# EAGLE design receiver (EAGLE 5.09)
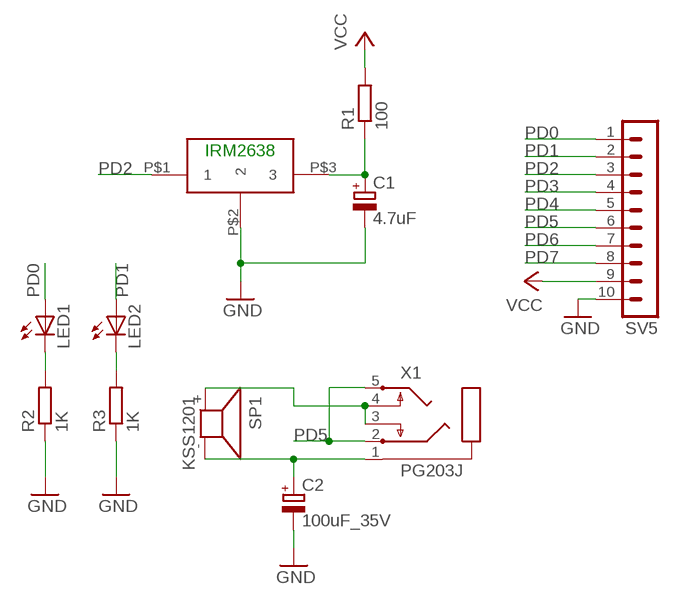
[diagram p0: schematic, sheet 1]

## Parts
C1  4.7uF  CPOL-EUE2.5-5  [E2,5-5]
C2  100uF_35V  CPOL-EUE1.8-4  [E1,8-4]
IRM2638  2638  [IRM2638]
LED1  LED5MM  [LED5MM]
LED2  LED5MM  [LED5MM]
R1  100  R-EU_0204/7  [0204/7]
R2  1K  R-EU_0204/7  [0204/7]
R3  1K  R-EU_0204/7  [0204/7]
SP1  KSS1201  [KSS1201]
SV5  MA10-1  [MA10-1]
X1  PG203J  [PG203J]

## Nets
GND: C1.- C2.- IRM2638.P$2 R2.1 R3.1 SV5.10
N$1: C2.+ SP1.- X1.1
N$2: C1.+ IRM2638.P$3 R1.1
N$3: SP1.+ X1.3 X1.4
N$4: LED1.K(C) R2.2
N$5: LED2.K(C) R3.2
PD0: LED1.A SV5.1
PD1: LED2.A SV5.2
PD2: IRM2638.P$1 SV5.3
PD3: SV5.4
PD4: SV5.5
PD5: SV5.6 X1.2 X1.5
PD6: SV5.7
PD7: SV5.8
VCC: R1.2 SV5.9

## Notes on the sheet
- IRM2638

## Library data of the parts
C1 = resistor:CPOL-EU: POLARIZED CAPACITOR, European symbol
C2 = rcl:CPOL-EU: POLARIZED CAPACITOR, European symbol
IRM2638 = 2638:2638
LED1 LED2 = led:LED: LED
R1-R3 = resistor:R-EU_: RESISTOR, European symbol
SP1 = buzzer:KSS1201: SPEAKER
SV5 = con-lstb:MA10-1: PIN HEADER
X1 = con-hirschmann:PG203J: MIC/HEADPHONE JACK KS-S stereo microphone/headphone jack PG203JN (Schukat)

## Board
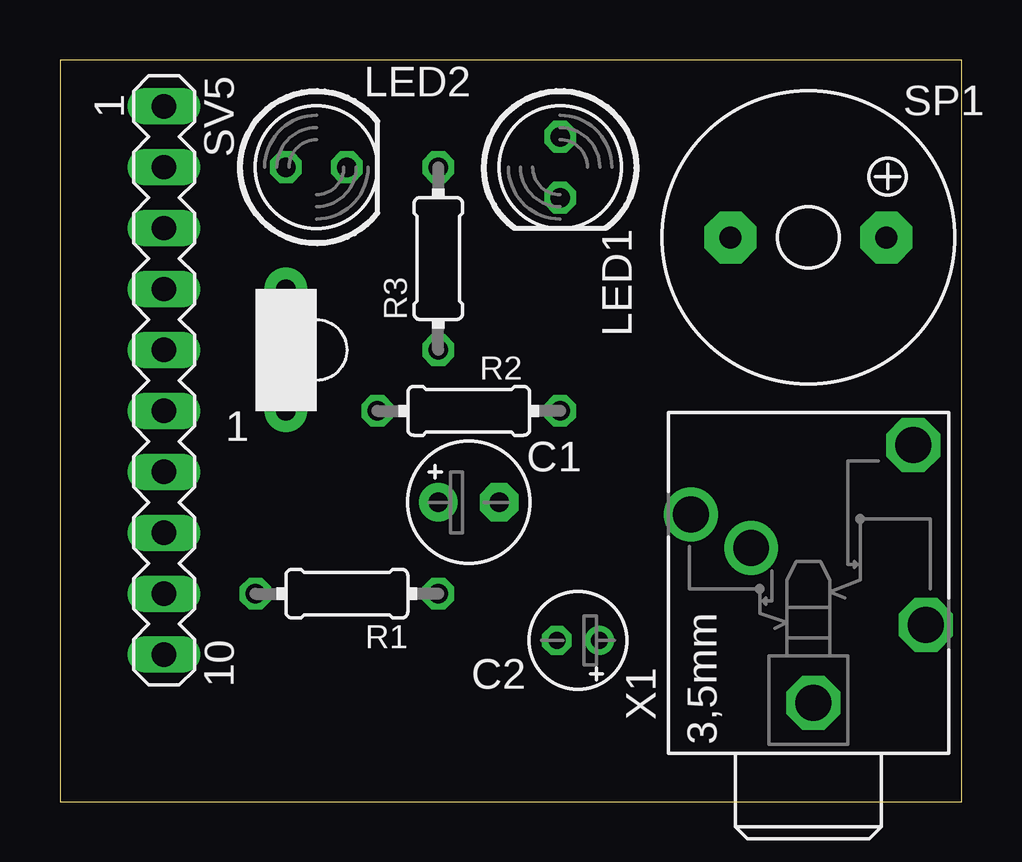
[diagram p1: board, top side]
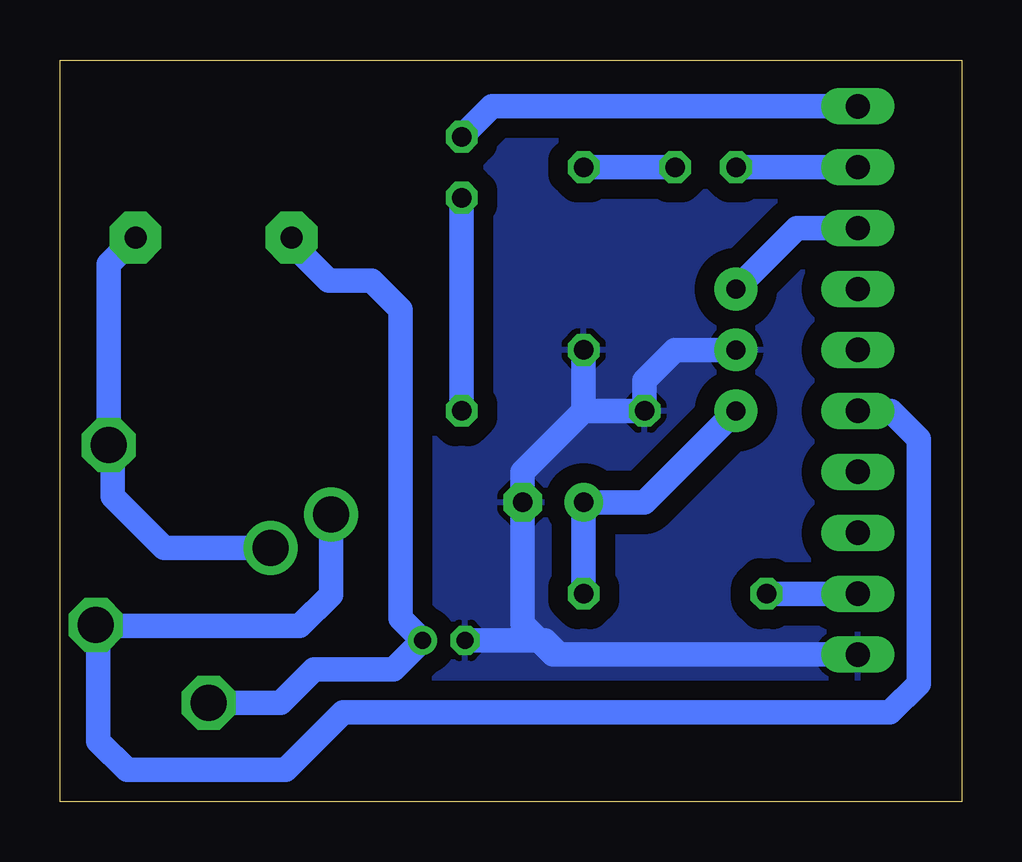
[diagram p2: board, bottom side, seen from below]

Size 37.6 x 30.93 mm. Coordinates in mm from the lower left corner, seen from the top.
Outline: 0,0 37.6,0 37.6,30.93 0,30.93 0,0
Copper layers (1*16): Top 0.035mm / dielectric 1.5mm / Bottom 0.035mm
Design rules "default": minimum track width 10mil, minimum drill 24mil, track to track 8mil, track to pad 8mil, pad to pad 8mil, via to via 8mil, smd to smd 8mil, copper to edge 40mil, drill to drill 8mil, minimum pad ring 10mil, minimum via ring 8mil, stop-mask expansion 4mil, vias tented up to drill 0mil, thermal gap 10mil

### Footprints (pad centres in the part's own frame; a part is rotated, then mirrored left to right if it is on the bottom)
E2,5-5 = drill 0.813 pad 1.6 round: + -1.27,0 | drill 0.813 pad 1.6 octagon: - 1.27,0
E1,8-4 = drill 0.711 pad 1.168 round: + -0.889,0 | drill 0.711 pad 1.168 octagon: - 0.889,0
IRM2638 = drill 0.8 pad 1.778 round: P$1 0,0; P$2 0,-2.54; P$3 0,-5.08
LED5MM = drill 0.813 octagon: A -1.27,0; K 1.27,0
0204/7 = drill 0.813 octagon: 1 -3.81,0; 2 3.81,0
KSS1201 = drill 0.914 pad 2.159 octagon: + 3.251,0; - -3.251,0
MA10-1 = drill 1.016 long: 1 -11.43,0; 2 -8.89,0; 3 -6.35,0; 4 -3.81,0; 5 -1.27,0; 6 1.27,0; 7 3.81,0; 8 6.35,0; 9 8.89,0; 10 11.43,0
PG203J = drill 1.499 octagon: 1 -5.004,-0.203; 4 5.74,-4.369; 5 -1.753,-4.902 | drill 1.499 round: 2 2.845,4.902; 3 1.448,2.388

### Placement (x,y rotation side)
C1  17.04,12.49 0 top
C2  21.6,6.73 180 top
IRM2638  9.42,21.38 0 top
LED1  20.85,26.46 270 top
LED2  10.69,26.46 0 top
R1  11.96,8.68 180 top
R2  17.04,16.3 0 top
R3  15.77,22.65 90 top
SP1  31.2,23.53 0 top
SV5  4.34,17.57 270 top
X1  31.2,9.13 90 top

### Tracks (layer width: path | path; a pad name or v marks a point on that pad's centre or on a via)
GND
  Bottom 1.016: SV5.10 16.8,6.14 | 16.8,6.14 17.04,6.14 18.31,7.41 C1.- 18.31,13.76 15.77,16.3 | 15.77,16.3 R2.1 13.23,17.57 11.96,18.84 IRM2638.P$2 | 15.77,16.3 R3.1 | C2.- 17.39,6.73 16.8,6.14
  pour Bottom (isolate 0.813): 0.6,30.13 37.2,30.13 37.2,0.13 0.6,0.13
N$1
  Bottom 1.016: SP1.- 27.95,23.28 26.4,21.73 24.6,21.73 23.4,20.53 23.4,7.64 C2.+ 23.69,5.53 27,5.53 28.4,4.13 X1.1
N$2
  Bottom 1.016: R1.1 C1.+ 13.23,12.49 IRM2638.P$3
N$3
  Bottom 1.016: X1.3 33.25,10.58 35.4,12.73 35.4,14.7 X1.4 35.57,22.41 SP1.+
N$4
  Bottom 1.016: R2.2 LED1.K
N$5
  Bottom 1.016: LED2.K R3.2
PD0
  Bottom 1.016: SV5.1 19.58,29 LED1.A
PD1
  Bottom 1.016: SV5.2 LED2.A
PD2
  Bottom 1.016: SV5.3 6.88,23.92 IRM2638.P$1
PD5
  Bottom 1.016: SV5.6 2.97,16.3 1.8,15.13 1.8,4.93 3,3.73 25.8,3.73 28.2,1.33 34.8,1.33 36,2.53 36,7.27 X1.5 36.05,7.33 27.6,7.33 26.3,8.63 X1.2
VCC
  Bottom 1.016: SV5.9 R1.2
